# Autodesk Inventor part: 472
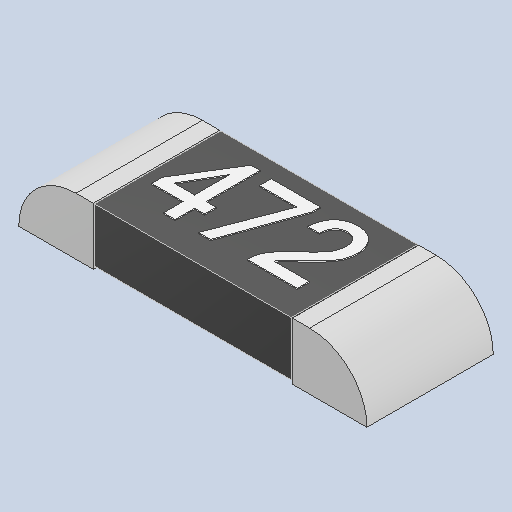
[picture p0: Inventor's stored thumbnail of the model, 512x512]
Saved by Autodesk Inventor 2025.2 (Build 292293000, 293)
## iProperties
Created: 2025-04
Part Number: 472
Material: Generic
Description: PART--DESC
Document SubType Name: Modeling
Designer: BennF
Density: 1 g/cm^3
Appearance: Default
Author: BennF
Revision Number: NONE
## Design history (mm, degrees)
feature "pin"
feature "Solid"
feature "4"
feature "7"
feature "2"
body "Solid1"
body "Solid2"
body "Solid3"
body "Solid4"
body "Solid5"
